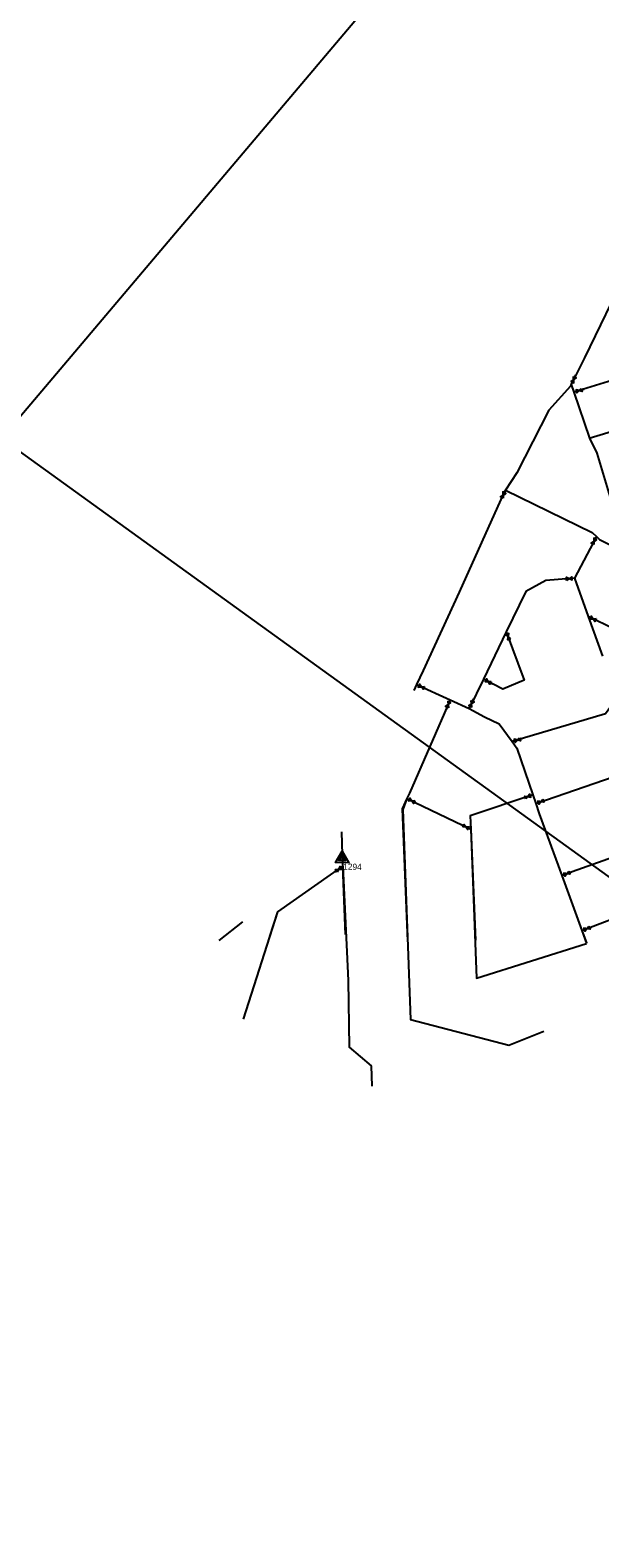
# Model space of a CAD drawing. Extents: x 349903 to 372392, y 368574 to 383062.
# Drawn here: x 361800 to 362258, y 371517 to 372729 of the extents above; entities that cross this region are included whole.
import ezdxf

# ---------------------------------------------------------------- set-up
doc = ezdxf.new("R2010")
doc.units = 0
for name, color, linetype in [('Niveau 1', 7, 'Continuous'), ('Niveau 10', 7, 'Continuous'), ('Niveau 2', 7, 'Continuous'), ('Niveau 20', 7, 'Continuous')]:
    doc.layers.add(name, color=color, linetype=linetype)

msp = doc.modelspace()

# ---------------------------------------------------------------- linework, layer by layer
at = {"layer": 'Niveau 1'}
for p, q in [((362235.182, 372444.101), (362236.108, 372445.991)), ((362238.034, 372449.924), (362238.871, 372451.631)), ((362237.321, 372437.801), (362239.335, 372438.41)), ((362243.527, 372439.678), (362245.347, 372440.228)), ((362179.312, 372353.161), (362178.445, 372351.469)), ((362182.269, 372358.931), (362181.309, 372357.058)), ((362252.323, 372315.967), (362251.433, 372314.287)), ((362255.361, 372321.695), (362254.375, 372319.836)), ((362231.33, 372287.722), (362229.435, 372287.562)), ((362237.791, 372288.266), (362235.694, 372288.09)), ((362248.825, 372257.346), (362250.745, 372256.484)), ((362254.741, 372254.692), (362256.476, 372253.914)), ((362182.911, 372245.211), (362183.645, 372243.239)), ((362185.174, 372239.135), (362185.838, 372237.353)), ((362164.47, 372207.189), (362166.338, 372206.22)), ((362170.226, 372204.204), (362171.914, 372203.329)), ((362110.684, 372202.777), (362112.601, 372201.91)), ((362116.593, 372200.107), (362118.325, 372199.324)), ((362155.815, 372189.43), (362156.634, 372191.146)), ((362135.225, 372184.531), (362134.47, 372182.786)), ((362137.799, 372190.482), (362136.963, 372188.551)), ((362153.019, 372183.58), (362153.927, 372185.479)), ((362187.617, 372156.898), (362189.633, 372157.5)), ((362193.83, 372158.754), (362195.652, 372159.298)), ((362102.87, 372111.227), (362104.758, 372110.297)), ((362108.686, 372108.361), (362110.392, 372107.521)), ((362198.101, 372111.962), (362196.299, 372111.355)), ((362204.246, 372114.03), (362202.252, 372113.359)), ((362206.565, 372107.249), (362208.561, 372107.916)), ((362212.714, 372109.306), (362214.517, 372109.909)), ((362148.525, 372089.179), (362146.811, 372090.002)), ((362154.369, 372086.37), (362152.473, 372087.282)), ((362046.151, 372053.003), (362044.594, 372051.913)), ((362049.732, 372055.509), (362051.463, 372056.721)), ((362227.548, 372049.261), (362229.529, 372049.97)), ((362233.653, 372051.447), (362235.442, 372052.088)), ((362243.732, 372004.951), (362245.699, 372005.7)), ((362249.791, 372007.259), (362251.568, 372007.935))]:
    msp.add_line(p, q, dxfattribs=at)
for points in [[(362236.894, 372450.478), (362239.163, 372449.375), (362234.975, 372446.561), (362237.238, 372445.444)], [(362243.157, 372440.89), (362243.894, 372438.477), (362238.982, 372439.628), (362239.704, 372437.21)], [(362180.442, 372352.586), (362178.193, 372353.73), (362182.431, 372356.468), (362180.189, 372357.626)], [(362253.446, 372315.376), (362251.213, 372316.551), (362255.489, 372319.23), (362253.263, 372320.419)], [(362231.44, 372286.459), (362231.221, 372288.972), (362235.787, 372286.825), (362235.583, 372289.34)], [(362255.256, 372255.851), (362254.231, 372253.545), (362251.277, 372257.636), (362250.236, 372255.337)], [(362186.361, 372239.581), (362183.999, 372238.693), (362184.839, 372243.669), (362182.471, 372242.795)], [(362117.111, 372201.264), (362116.079, 372198.961), (362113.137, 372203.06), (362112.09, 372200.764)], [(362170.806, 372205.332), (362169.652, 372203.088), (362166.934, 372207.34), (362165.765, 372205.103)], [(362136.39, 372184.031), (362134.071, 372185.026), (362138.122, 372188.034), (362135.809, 372189.044)], [(362154.669, 372189.973), (362156.949, 372188.893), (362152.788, 372186.038), (362155.062, 372184.943)], [(362193.463, 372159.967), (362194.193, 372157.552), (362189.284, 372158.719), (362189.998, 372156.299)], [(362109.243, 372109.501), (362108.135, 372107.234), (362105.331, 372111.428), (362104.208, 372109.168)], [(362198.509, 372110.761), (362197.697, 372113.15), (362202.643, 372112.152), (362201.846, 372114.547)], [(362212.308, 372110.507), (362213.116, 372108.117), (362208.172, 372109.124), (362208.964, 372106.728)], [(362147.979, 372088.034), (362149.065, 372090.312), (362151.911, 372086.145), (362153.011, 372088.416)], [(362046.882, 372051.966), (362045.428, 372054.028), (362050.455, 372054.468), (362049.015, 372056.539)], [(362233.221, 372052.639), (362234.079, 372050.266), (362229.115, 372051.169), (362229.958, 372048.79)], [(362249.336, 372008.442), (362250.242, 372006.087), (362245.26, 372006.89), (362246.151, 372004.529)]]:
    msp.add_lwpolyline(points, close=True, dxfattribs=at)
at = {"layer": 'Niveau 10'}
for p, q in [((362287.189, 372412.164), (362249.62, 372400.582)), ((362206.565, 372107.249), (362269.694, 372128.837)), ((362102.87, 372111.227), (362154.369, 372086.37)), ((362051.463, 372056.721), (362050.493, 372084.452)), ((362324.166, 372083.535), (362227.548, 372049.261)), ((362053.615, 372001.738), (362051.463, 372056.721)), ((362243.732, 372004.951), (362296.22, 372025.084)), ((361970.659, 372011.895), (361951.68, 371997.105)), ((362243.732, 372004.951), (362247.355, 371995.042))]:
    msp.add_line(p, q, dxfattribs=at)
for points in [[(362788.261, 373505.998), (362567.264, 373276.164), (362165.59, 372859.866), (361437.718, 372000.178)], [(362279.905, 372535.679), (362245.71, 372465.405), (362235.182, 372444.101)], [(362275.668, 372449.533), (362237.321, 372437.801)], [(362235.182, 372444.101), (362234.505, 372442.732), (362217.083, 372423.372), (362191.462, 372372.912), (362182.269, 372358.931)], [(362235.182, 372444.101), (362237.321, 372437.801)], [(362237.321, 372437.801), (362249.852, 372400.889), (362255.743, 372388.781), (362266.193, 372353.822)], [(362182.269, 372358.931), (362180.873, 372356.807), (362144.85, 372276.911), (362115.864, 372214.149), (362110.684, 372202.777)], [(362182.269, 372358.931), (362251.87, 372325.01), (362255.361, 372321.695)], [(362255.361, 372321.695), (362237.791, 372288.266)], [(362255.361, 372321.695), (362257.869, 372319.313), (362280.706, 372308.017)], [(362237.791, 372288.266), (362214.826, 372286.324), (362198.604, 372277.568), (362182.911, 372245.211)], [(362237.791, 372288.266), (362248.825, 372257.346)], [(362248.825, 372257.346), (362260.16, 372225.583)], [(362270.042, 372247.295), (362248.825, 372257.346)], [(362182.911, 372245.211), (362197.191, 372206.255), (362179.996, 372199.171), (362164.47, 372207.189)], [(362182.911, 372245.211), (362164.47, 372207.189)], [(362164.47, 372207.189), (362153.019, 372183.58)], [(362110.684, 372202.777), (362108.518, 372198.02)], [(362110.684, 372202.777), (362137.799, 372190.482)], [(362274.091, 372194.892), (362262.702, 372179.101), (362187.617, 372156.898)], [(362137.799, 372190.482), (362104.942, 372115.485), (362102.87, 372111.227)], [(362137.799, 372190.482), (362153.019, 372183.58)], [(362153.019, 372183.58), (362165.475, 372176.704), (362177.259, 372171.261), (362187.617, 372156.898)], [(362187.617, 372156.898), (362191.355, 372151.715), (362204.246, 372114.03)], [(362102.87, 372111.227), (362099.19, 372102.775), (362103.333, 371996.578)], [(362102.87, 372111.227), (362099.556, 372102.387), (362105.84, 371933.504), (362184.84, 371912.843), (362212.967, 371924.065)], [(362204.246, 372114.03), (362153.897, 372097.325), (362154.369, 372086.37)], [(362204.246, 372114.03), (362206.565, 372107.249)], [(362206.565, 372107.249), (362209.461, 372098.783), (362227.548, 372049.261)], [(362154.369, 372086.37), (362158.806, 371966.742), (362247.547, 371994.507)], [(362154.369, 372086.37), (362158.205, 371997.27)], [(361971.449, 371933.788), (361999.15, 372019.903), (362051.463, 372056.721)], [(361992.643, 372000.3), (361999.099, 372020.066), (362051.463, 372056.721)], [(362051.463, 372056.721), (362055.524, 371964.954), (362056.527, 371911.198), (362074.043, 371896.138), (362074.669, 371879.823)], [(362227.548, 372049.261), (362243.732, 372004.951)], [(362243.732, 372004.951), (362247.547, 371994.507)]]:
    msp.add_lwpolyline(points, dxfattribs=at)
at = {"layer": 'Niveau 2'}
for points in [[(362050.932, 372068.917), (362056.122, 372059.493), (362045.366, 372059.711)], [(362050.906, 372065.935), (362053.499, 372061.224), (362048.121, 372061.335)]]:
    msp.add_lwpolyline(points, close=True, dxfattribs=at)
at = {"layer": 'Niveau 20'}
for points in [[(365165.277, 375764.604), (367014.204, 373077.161), (365116.287, 370509.391), (363702.153, 371011.781), (361432.095, 372649.199), (361533.395, 373713.771)], [(361432.095, 372649.199), (359273.68, 370583.819), (361376.274, 368741.723), (363534.689, 368816.151), (365116.287, 370509.391), (363702.153, 371011.781)]]:
    msp.add_lwpolyline(points, close=True, dxfattribs=at)

# ---------------------------------------------------------------- texts
at = {"layer": 'Niveau 2'}
msp.add_text('1294', height=5, rotation=359, dxfattribs=at).set_placement((362051.631, 372053.911))

doc.saveas('drawing.dxf')
